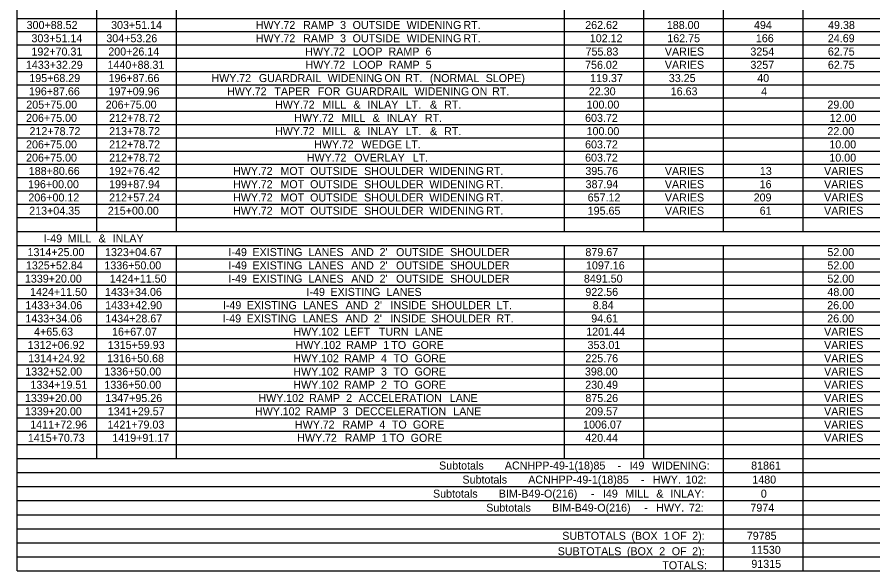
# Model space of a CAD drawing. Extents: x 1226590 to 1228573, y 151304 to 154224.
# Drawn here: x 1226590 to 1227125, y 152628 to 152974 of the extents above; entities that cross this region are included whole.
import ezdxf

# ---------------------------------------------------------------- set-up
doc = ezdxf.new("R2010")
doc.units = 0
doc.layers.add('R_Dimension', color=7, linetype='Continuous')

msp = doc.modelspace()

# ---------------------------------------------------------------- linework, layer by layer
at = {"layer": 'R_Dimension'}
for p, q in [((1226590.27, 152627.62), (1226590.27, 154214.43)), ((1226640, 152839.68), (1226640, 153113.65)), ((1226689.72, 152839.68), (1226689.72, 153113.65)), ((1226932.01, 152839.68), (1226932.01, 153113.65)), ((1226981.73, 152839.68), (1226981.73, 153113.65)), ((1227031.46, 152839.68), (1227031.46, 153113.65)), ((1227081.18, 152839.68), (1227081.18, 153113.65)), ((1226590.27, 152972.77), (1228572.93, 152972.77)), ((1226590.27, 152964.48), (1228572.93, 152964.48)), ((1226590.27, 152956.19), (1228572.93, 152956.19)), ((1226590.27, 152947.9), (1228572.93, 152947.9)), ((1226590.27, 152939.62), (1228572.93, 152939.62)), ((1226590.27, 152931.33), (1228572.93, 152931.33)), ((1226590.27, 152923.04), (1228572.93, 152923.04)), ((1226590.27, 152914.75), (1228572.93, 152914.75)), ((1226590.27, 152906.47), (1228572.93, 152906.47)), ((1226590.27, 152898.18), (1228572.93, 152898.18)), ((1226590.27, 152889.89), (1228572.93, 152889.89)), ((1226590.27, 152881.6), (1228572.93, 152881.6)), ((1226590.27, 152873.32), (1228572.93, 152873.32)), ((1226590.27, 152865.03), (1228572.93, 152865.03)), ((1226590.27, 152856.74), (1228572.93, 152856.74)), ((1226590.27, 152848.45), (1228572.93, 152848.45)), ((1226590.27, 152839.68), (1228572.93, 152839.68)), ((1226590.27, 152830.9), (1228572.93, 152830.9)), ((1226640, 152697.82), (1226640, 152830.9)), ((1226689.72, 152697.82), (1226689.72, 152830.9)), ((1226932.01, 152697.82), (1226932.01, 152830.9)), ((1226981.73, 152697.82), (1226981.73, 152830.9)), ((1227031.46, 152627.62), (1227031.46, 152830.9)), ((1227081.18, 152627.62), (1227081.18, 152830.9)), ((1226590.27, 152822.62), (1228572.93, 152822.62)), ((1226590.27, 152814.33), (1228572.93, 152814.33)), ((1226590.27, 152806.04), (1228572.93, 152806.04)), ((1226590.27, 152797.75), (1228572.93, 152797.75)), ((1226590.27, 152789.47), (1228572.93, 152789.47)), ((1226590.27, 152781.18), (1228572.93, 152781.18)), ((1226590.27, 152772.89), (1228572.93, 152772.89)), ((1226590.27, 152764.6), (1228572.93, 152764.6)), ((1226590.27, 152756.32), (1228572.93, 152756.32)), ((1226590.27, 152748.03), (1228572.93, 152748.03)), ((1226590.27, 152739.74), (1228572.93, 152739.74)), ((1226590.27, 152731.45), (1228572.93, 152731.45)), ((1226590.27, 152723.17), (1228572.93, 152723.17)), ((1226590.27, 152714.88), (1228572.93, 152714.88)), ((1226590.27, 152706.59), (1228572.93, 152706.59)), ((1226590.27, 152697.82), (1228572.93, 152697.82)), ((1226590.27, 152689.04), (1228572.93, 152689.04)), ((1226590.27, 152680.27), (1228572.93, 152680.27)), ((1226590.27, 152671.49), (1228572.93, 152671.49)), ((1226590.27, 152662.72), (1228572.93, 152662.72)), ((1226590.27, 152653.94), (1228572.93, 152653.94)), ((1226590.27, 152645.17), (1228572.93, 152645.17)), ((1226590.27, 152636.39), (1228572.93, 152636.39)), ((1226590.27, 152627.62), (1228572.93, 152627.62))]:
    msp.add_line(p, q, dxfattribs=at)

# ---------------------------------------------------------------- texts
for s, p in [('300+88.52', (1226596.2, 152966.12)), ('303+51.14', (1226648.95, 152966.12)), ('HWY.', (1226739.25, 152966.12)), (' 72', (1226754.68, 152966.12)), (' RAMP', (1226767.01, 152966.12)), (' 3', (1226790.08, 152966.12)), (' OUTSIDE', (1226797.91, 152966.12)), (' WIDENING', (1226831.65, 152966.12)), (' RT.', (1226867.08, 152966.12)), ('262.62', (1226945.02, 152966.12)), ('188.00', (1226995.98, 152966.12)), ('494', (1227050.41, 152966.12)), ('49.38', (1227096.68, 152966.12)), ('303+51.14', (1226599.23, 152957.84)), ('304+53.26', (1226645.98, 152957.84)), ('HWY.', (1226739.25, 152957.84)), (' 72', (1226754.68, 152957.84)), (' RAMP', (1226767.01, 152957.84)), (' 3', (1226790.08, 152957.84)), (' OUTSIDE', (1226797.91, 152957.84)), (' WIDENING', (1226831.65, 152957.84)), (' RT.', (1226867.08, 152957.84)), ('102.12', (1226947.89, 152957.84)), ('162.75', (1226996.28, 152957.84)), ('166', (1227051.58, 152957.84)), ('24.69', (1227096.54, 152957.84)), ('192+70.31', (1226599.23, 152949.55)), ('200+26.14', (1226647.22, 152949.55)), ('HWY.', (1226770.21, 152949.55)), (' 72', (1226785.65, 152949.55)), (' LOOP', (1226797.97, 152949.55)), (' RAMP', (1226820.33, 152949.55)), (' 6', (1226843.4, 152949.55)), ('755.83', (1226945.26, 152949.55)), ('VARIES', (1226994.74, 152949.55)), ('3254', (1227048.17, 152949.55)), ('62.75', (1227096.56, 152949.55)), ('1433+32.29', (1226595.74, 152941.26)), ('1440+88.31', (1226646.71, 152941.26)), ('HWY.', (1226770.35, 152941.26)), (' 72', (1226785.79, 152941.26)), (' LOOP', (1226798.11, 152941.26)), (' RAMP', (1226820.47, 152941.26)), (' 5', (1226843.54, 152941.26)), ('756.02', (1226944.94, 152941.26)), ('VARIES', (1226994.74, 152941.26)), ('3257', (1227048.17, 152941.26)), ('62.75', (1227096.56, 152941.26)), ('195+68.29', (1226597.87, 152932.97)), ('196+87.66', (1226647.36, 152932.97)), ('HWY.', (1226711.63, 152932.97)), (' 72', (1226727.06, 152932.97)), (' GUARDRAIL', (1226739.39, 152932.97)), (' WIDENING', (1226782.34, 152932.97)), (' ON', (1226817.77, 152932.97)), (' RT.', (1226830.77, 152932.97)), (' (NORMAL', (1226846.16, 152932.97)), (' SLOPE)', (1226881, 152932.97)), ('119.37', (1226948.09, 152932.97)), ('33.25', (1226997.23, 152932.97)), ('40', (1227052.44, 152932.97)), ('196+87.66', (1226597.63, 152924.69)), ('197+09.96', (1226647.4, 152924.69)), ('HWY.', (1226721.32, 152924.69)), (' 72', (1226736.75, 152924.69)), (' TAPER', (1226749.07, 152924.69)), (' FOR', (1226776.16, 152924.69)), (' GUARDRAIL', (1226793.64, 152924.69)), (' WIDENING', (1226836.59, 152924.69)), (' ON', (1226872.03, 152924.69)), (' RT.', (1226885.02, 152924.69)), ('22.30', (1226947.28, 152924.69)), ('16.63', (1226998.41, 152924.69)), ('4', (1227054.9, 152924.69)), ('205+75.00', (1226595.98, 152916.4)), ('206+75.00', (1226645.59, 152916.4)), ('HWY.', (1226751.32, 152916.4)), (' 72', (1226766.75, 152916.4)), (' MILL', (1226779.07, 152916.4)), (' &', (1226798.4, 152916.4)), (' INLAY', (1226807.18, 152916.4)), (' LT.', (1226831.08, 152916.4)), (' &', (1226846.24, 152916.4)), (' RT.', (1226855.02, 152916.4)), ('100.00', (1226945.87, 152916.4)), ('29.00', (1227096.26, 152916.4)), ('206+75.00', (1226595.86, 152908.11)), ('212+78.72', (1226647.73, 152908.11)), ('HWY.', (1226763.29, 152908.11)), (' 72', (1226778.72, 152908.11)), (' MILL', (1226791.04, 152908.11)), (' &', (1226810.37, 152908.11)), (' INLAY', (1226819.15, 152908.11)), (' RT.', (1226843.05, 152908.11)), ('603.72', (1226944.94, 152908.11)), ('12.00', (1227097.68, 152908.11)), ('212+78.72', (1226598.01, 152899.82)), ('213+78.72', (1226647.73, 152899.82)), ('HWY.', (1226751.32, 152899.82)), (' 72', (1226766.75, 152899.82)), (' MILL', (1226779.07, 152899.82)), (' &', (1226798.4, 152899.82)), (' INLAY', (1226807.18, 152899.82)), (' LT.', (1226831.08, 152899.82)), (' &', (1226846.24, 152899.82)), (' RT.', (1226855.02, 152899.82)), ('100.00', (1226945.87, 152899.82)), ('22.00', (1227096.26, 152899.82)), ('206+75.00', (1226595.86, 152891.54)), ('212+78.72', (1226647.73, 152891.54)), ('HWY.', (1226775.73, 152891.54)), (' 72', (1226791.16, 152891.54)), (' WEDGE', (1226803.48, 152891.54)), (' LT.', (1226830.84, 152891.54)), ('603.72', (1226944.94, 152891.54)), ('10.00', (1227097.48, 152891.54)), ('206+75.00', (1226595.86, 152883.25)), ('212+78.72', (1226647.73, 152883.25)), ('HWY.', (1226771.16, 152883.25)), (' 72', (1226786.59, 152883.25)), (' OVERLAY', (1226798.92, 152883.25)), (' LT.', (1226835.41, 152883.25)), ('603.72', (1226944.94, 152883.25)), ('10.00', (1227097.48, 152883.25)), ('188+80.66', (1226597.55, 152874.96)), ('192+76.42', (1226647.61, 152874.96)), ('HWY.', (1226725.1, 152874.96)), (' 72', (1226740.53, 152874.96)), (' MOT', (1226752.85, 152874.96)), (' OUTSIDE', (1226771.36, 152874.96)), (' SHOULDER', (1226805.1, 152874.96)), (' WIDENING', (1226845.8, 152874.96)), (' RT.', (1226881.24, 152874.96)), ('395.76', (1226945.12, 152874.96)), ('VARIES', (1226994.74, 152874.96)), ('13', (1227054.08, 152874.96)), ('VARIES', (1227094.19, 152874.96)), ('196+00.00', (1226597.08, 152866.67)), ('199+87.94', (1226647.73, 152866.67)), ('HWY.', (1226725.1, 152866.67)), (' 72', (1226740.53, 152866.67)), (' MOT', (1226752.85, 152866.67)), (' OUTSIDE', (1226771.36, 152866.67)), (' SHOULDER', (1226805.1, 152866.67)), (' WIDENING', (1226845.8, 152866.67)), (' RT.', (1226881.24, 152866.67)), ('387.94', (1226945.26, 152866.67)), ('VARIES', (1226994.74, 152866.67)), ('16', (1227053.94, 152866.67)), ('VARIES', (1227094.19, 152866.67)), ('206+00.12', (1226597.3, 152858.39)), ('212+57.24', (1226647.73, 152858.39)), ('HWY.', (1226725.1, 152858.39)), (' 72', (1226740.53, 152858.39)), (' MOT', (1226752.85, 152858.39)), (' OUTSIDE', (1226771.36, 152858.39)), (' SHOULDER', (1226805.1, 152858.39)), (' WIDENING', (1226845.8, 152858.39)), (' RT.', (1226881.24, 152858.39)), ('657.12', (1226946.56, 152858.39)), ('VARIES', (1226994.74, 152858.39)), ('209', (1227050.2, 152858.39)), ('VARIES', (1227094.19, 152858.39)), ('213+04.35', (1226597.81, 152850.1)), ('215+00.00', (1226646.92, 152850.1)), ('HWY.', (1226725.1, 152850.1)), (' 72', (1226740.53, 152850.1)), (' MOT', (1226752.85, 152850.1)), (' OUTSIDE', (1226771.36, 152850.1)), (' SHOULDER', (1226805.1, 152850.1)), (' WIDENING', (1226845.8, 152850.1)), (' RT.', (1226881.24, 152850.1)), ('195.65', (1226946.56, 152850.1)), ('VARIES', (1226994.74, 152850.1)), ('61', (1227053.96, 152850.1)), ('VARIES', (1227094.19, 152850.1)), ('I-49', (1226606.85, 152832.79)), (' MILL', (1226619.96, 152832.79)), (' &', (1226639.29, 152832.79)), (' INLAY', (1226648.07, 152832.79)), ('1314+25.00', (1226596.77, 152824.26)), ('1323+04.67', (1226645.17, 152824.26)), ('I-49', (1226722.24, 152824.26)), (' EXISTING', (1226735.35, 152824.26)), (' LANES', (1226770.39, 152824.26)), (' AND', (1226797.04, 152824.26)), (" 2'", (1226814.76, 152824.26)), (' OUTSIDE', (1226825.04, 152824.26)), (' SHOULDER', (1226858.78, 152824.26)), ('879.67', (1226945.14, 152824.26)), ('52.00', (1227096.26, 152824.26)), ('1325+52.84', (1226595.76, 152815.97)), ('1336+50.00', (1226644.76, 152815.97)), ('I-49', (1226722.24, 152815.97)), (' EXISTING', (1226735.35, 152815.97)), (' LANES', (1226770.39, 152815.97)), (' AND', (1226797.04, 152815.97)), (" 2'", (1226814.76, 152815.97)), (' OUTSIDE', (1226825.04, 152815.97)), (' SHOULDER', (1226858.78, 152815.97)), ('1097.16', (1226945.51, 152815.97)), ('52.00', (1227096.26, 152815.97)), ('1339+20.00', (1226595.15, 152807.69)), ('1424+11.50', (1226648.11, 152807.69)), ('I-49', (1226722.24, 152807.69)), (' EXISTING', (1226735.35, 152807.69)), (' LANES', (1226770.39, 152807.69)), (' AND', (1226797.04, 152807.69)), (" 2'", (1226814.76, 152807.69)), (' OUTSIDE', (1226825.04, 152807.69)), (' SHOULDER', (1226858.78, 152807.69)), ('8491.50', (1226944.21, 152807.69)), ('52.00', (1227096.26, 152807.69)), ('1424+11.50', (1226598.38, 152799.4)), ('1433+34.06', (1226645.15, 152799.4)), ('I-49', (1226770.96, 152799.4)), (' EXISTING', (1226784.07, 152799.4)), (' LANES', (1226819.11, 152799.4)), ('922.56', (1226945.12, 152799.4)), ('48.00', (1227096.26, 152799.4)), ('1433+34.06', (1226595.43, 152791.11)), ('1433+42.90', (1226645.27, 152791.11)), ('I-49', (1226718.76, 152791.11)), (' EXISTING', (1226731.87, 152791.11)), (' LANES', (1226766.91, 152791.11)), (' AND', (1226793.56, 152791.11)), (" 2'", (1226811.28, 152791.11)), (' INSIDE', (1226821.55, 152791.11)), (' SHOULDER', (1226847.1, 152791.11)), (' LT.', (1226887.81, 152791.11)), ('8.84', (1226949.74, 152791.11)), ('26.00', (1227096.14, 152791.11)), ('1433+34.06', (1226595.43, 152782.82)), ('1434+28.67', (1226645.37, 152782.82)), ('I-49', (1226718.64, 152782.82)), (' EXISTING', (1226731.75, 152782.82)), (' LANES', (1226766.79, 152782.82)), (' AND', (1226793.44, 152782.82)), (" 2'", (1226811.16, 152782.82)), (' INSIDE', (1226821.43, 152782.82)), (' SHOULDER', (1226846.99, 152782.82)), (' RT.', (1226887.69, 152782.82)), ('94.61', (1226948.8, 152782.82)), ('26.00', (1227096.14, 152782.82)), ('4+65.63', (1226600.84, 152774.54)), ('16+67.07', (1226649.54, 152774.54)), ('HWY.', (1226762.75, 152774.54)), (' 102', (1226778.19, 152774.54)), (' LEFT', (1226792.56, 152774.54)), (' TURN', (1226814.29, 152774.54)), (' LANE', (1226836.81, 152774.54)), ('1201.44', (1226945.65, 152774.54)), ('VARIES', (1227094.19, 152774.54)), ('1312+06.92', (1226596.86, 152766.25)), ('1315+59.93', (1226646.9, 152766.25)), ('HWY.', (1226764.15, 152766.25)), (' 102', (1226779.58, 152766.25)), (' RAMP', (1226793.95, 152766.25)), (' 1', (1226817.03, 152766.25)), (' TO', (1226822.03, 152766.25)), (' GORE', (1226835.17, 152766.25)), ('353.01', (1226946.48, 152766.25)), ('VARIES', (1227094.19, 152766.25)), ('1314+24.92', (1226597.18, 152757.96)), ('1316+50.68', (1226646.47, 152757.96)), ('HWY.', (1226762.73, 152757.96)), (' 102', (1226778.17, 152757.96)), (' RAMP', (1226792.54, 152757.96)), (' 4', (1226815.61, 152757.96)), (' TO', (1226823.44, 152757.96)), (' GORE', (1226836.59, 152757.96)), ('225.76', (1226945.12, 152757.96)), ('VARIES', (1227094.19, 152757.96)), ('1332+52.00', (1226595.35, 152749.67)), ('1336+50.00', (1226644.76, 152749.67)), ('HWY.', (1226762.73, 152749.67)), (' 102', (1226778.17, 152749.67)), (' RAMP', (1226792.54, 152749.67)), (' 3', (1226815.61, 152749.67)), (' TO', (1226823.44, 152749.67)), (' GORE', (1226836.59, 152749.67)), ('398.00', (1226944.84, 152749.67)), ('VARIES', (1227094.19, 152749.67)), ('1334+19.51', (1226598.6, 152741.39)), ('1336+50.00', (1226644.76, 152741.39)), ('HWY.', (1226762.73, 152741.39)), (' 102', (1226778.17, 152741.39)), (' RAMP', (1226792.54, 152741.39)), (' 2', (1226815.61, 152741.39)), (' TO', (1226823.44, 152741.39)), (' GORE', (1226836.59, 152741.39)), ('230.49', (1226945.04, 152741.39)), ('VARIES', (1227094.19, 152741.39)), ('1339+20.00', (1226595.15, 152733.1)), ('1347+95.26', (1226645.35, 152733.1)), ('HWY.', (1226740.96, 152733.1)), (' 102', (1226756.4, 152733.1)), (' RAMP', (1226770.77, 152733.1)), (' 2', (1226793.84, 152733.1)), (' ACCELERATION', (1226801.67, 152733.1)), (' LANE', (1226858.6, 152733.1)), ('875.26', (1226945.12, 152733.1)), ('VARIES', (1227094.19, 152733.1)), ('1339+20.00', (1226595.15, 152724.81)), ('1341+29.57', (1226646.9, 152724.81)), ('HWY.', (1226738.8, 152724.81)), (' 102', (1226754.23, 152724.81)), (' RAMP', (1226768.6, 152724.81)), (' 3', (1226791.67, 152724.81)), (' DECCELERATION', (1226799.51, 152724.81)), (' LANE', (1226860.77, 152724.81)), ('209.57', (1226945.06, 152724.81)), ('VARIES', (1227094.19, 152724.81)), ('1411+72.96', (1226598.46, 152716.52)), ('1421+79.03', (1226646.71, 152716.52)), ('HWY.', (1226763.76, 152716.52)), (' 72', (1226779.19, 152716.52)), (' RAMP', (1226791.51, 152716.52)), (' 4', (1226814.58, 152716.52)), (' TO', (1226822.42, 152716.52)), (' GORE', (1226835.57, 152716.52)), ('1006.07', (1226943.72, 152716.52)), ('VARIES', (1227094.19, 152716.52)), ('1415+70.73', (1226596.98, 152708.24)), ('1419+91.17', (1226649.74, 152708.24)), ('HWY.', (1226765.17, 152708.24)), (' 72', (1226780.61, 152708.24)), (' RAMP', (1226792.93, 152708.24)), (' 1', (1226816, 152708.24)), (' TO', (1226821, 152708.24)), (' GORE', (1226834.15, 152708.24)), ('420.44', (1226945.06, 152708.24)), ('VARIES', (1227094.19, 152708.24)), ('Subtotals', (1226853.75, 152690.93)), (' ACNHPP-49-1(18)85', (1226892.96, 152690.93)), (' -', (1226963.39, 152690.93)), (' I49', (1226970.83, 152690.93)), (' WIDENING:', (1226984.85, 152690.93)), ('81861', (1227048.64, 152690.93)), ('Subtotals', (1226868.35, 152682.15)), (' ACNHPP-49-1(18)85', (1226907.56, 152682.15)), (' HWY.', (1226985.44, 152682.15)), (' 102:', (1227005.87, 152682.15)), ('1480', (1227049.37, 152682.15)), (' -', (1226978, 152682.15)), ('Subtotals', (1226849.97, 152673.38)), (' BIM-B49-O(216)', (1226889.18, 152673.38)), (' -', (1226946.78, 152673.38)), (' I49', (1226954.22, 152673.38)), (' MILL', (1226968.23, 152673.38)), (' &', (1226987.56, 152673.38)), (' INLAY:', (1226996.34, 152673.38)), ('0', (1227054.69, 152673.38)), ('Subtotals', (1226883.23, 152664.6)), (' BIM-B49-O(216)', (1226922.45, 152664.6)), (' -', (1226980.04, 152664.6)), (' HWY.', (1226987.49, 152664.6)), (' 72:', (1227007.92, 152664.6)), ('7974', (1227048.17, 152664.6)), ('SUBTOTALS', (1226930.67, 152647.05)), (' (BOX', (1226972.01, 152647.05)), (' 1', (1226992.21, 152647.05)), (' OF', (1226997.21, 152647.05)), (' 2):', (1227009.97, 152647.05)), ('79785', (1227045.93, 152647.05)), ('11530', (1227048.54, 152638.28)), ('SUBTOTALS', (1226927.84, 152637.39)), (' (BOX', (1226969.18, 152637.39)), (' 2', (1226989.38, 152637.39)), (' OF', (1226997.21, 152637.39)), (' 2):', (1227009.97, 152637.39)), ('TOTALS:', (1226993.16, 152628.62)), ('91315', (1227048.76, 152629.5))]:
    msp.add_text(s, height=5, dxfattribs=at).set_placement(p)

doc.saveas('drawing.dxf')
